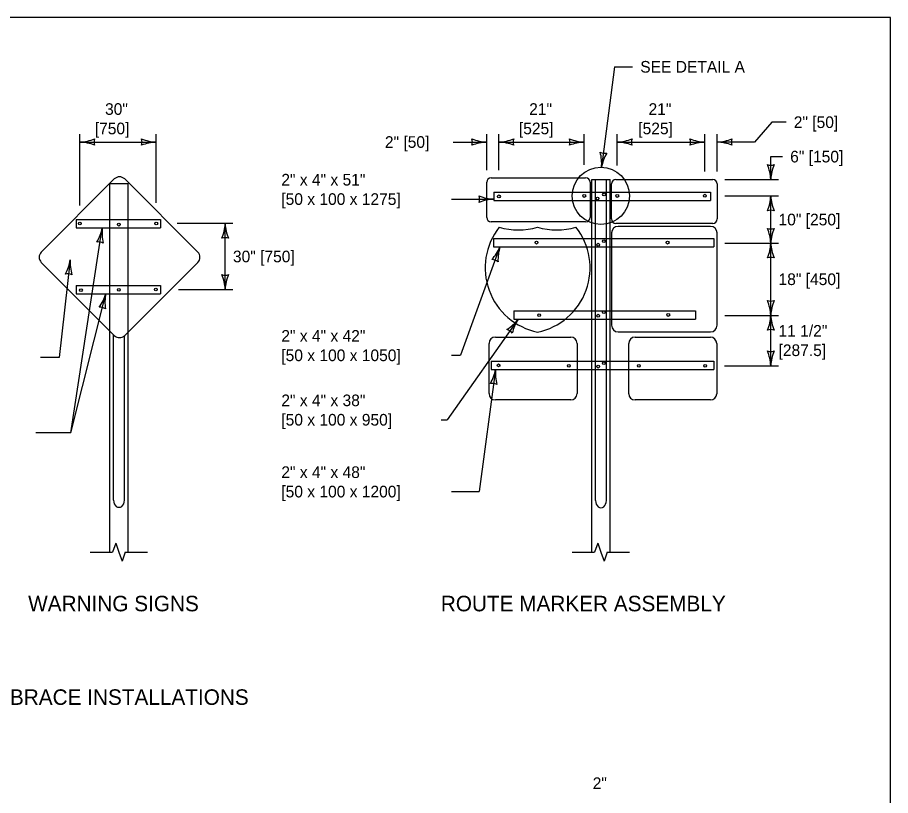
# Model space of a CAD drawing. Extents: x 49991.4 to 50021, y 49987.6 to 50011.4.
# Drawn here: x 50004.115 to 50008.615, y 50007.252 to 50011.263 of the extents above; entities that cross this region are included whole.
import ezdxf

# ---------------------------------------------------------------- set-up
doc = ezdxf.new("R2010")
doc.units = 0
for name, color, linetype in [('Level 1', 7, 'Continuous'), ('Level 2', 7, 'Continuous'), ('Level 3', 7, 'Continuous'), ('Level 4', 7, 'Continuous'), ('Level 6', 7, 'Continuous')]:
    doc.layers.add(name, color=color, linetype=linetype)

msp = doc.modelspace()

# ---------------------------------------------------------------- linework, layer by layer
at = {"layer": 'Level 1'}
for p, q in [((50006.5559, 50010.4356), (50007.0433, 50010.4356)), ((50004.6142, 50010.4302), (50004.2379, 50010.0538)), ((50005.0444, 50010.0538), (50004.668, 50010.4302)), ((50006.5332, 50010.2317), (50006.5332, 50010.413)), ((50007.0659, 50010.413), (50007.0659, 50010.2317)), ((50007.0744, 50008.5067), (50007.0744, 50010.4281)), ((50007.0744, 50010.4281), (50007.1696, 50010.4281)), ((50007.0942, 50008.7725), (50007.0942, 50010.4281)), ((50007.1502, 50008.7725), (50007.1502, 50010.4281)), ((50007.1696, 50008.5067), (50007.1696, 50010.4281)), ((50007.176, 50010.2241), (50007.176, 50010.4054)), ((50007.1988, 50010.4281), (50007.6985, 50010.4281)), ((50007.7212, 50010.4054), (50007.7212, 50010.2241)), ((50007.0433, 50010.209), (50006.5559, 50010.209)), ((50007.6985, 50010.2014), (50007.1988, 50010.2014)), ((50007.6868, 50010.1861), (50007.2108, 50010.1861)), ((50007.1768, 50010.1521), (50007.1768, 50009.6761)), ((50007.7208, 50009.6761), (50007.7208, 50010.1521)), ((50004.2379, 50010.0001), (50004.6142, 50009.6237)), ((50004.9757, 50009.9314), (50005.0444, 50010.0001)), ((50004.668, 50009.6237), (50004.9757, 50009.9315)), ((50004.5905, 50008.5067), (50004.5905, 50009.6474)), ((50004.6103, 50008.7748), (50004.6103, 50009.6276)), ((50004.6857, 50008.5067), (50004.6857, 50009.6414)), ((50007.2108, 50009.6421), (50007.6868, 50009.6421)), ((50004.6663, 50008.7748), (50004.6663, 50009.6221)), ((50006.5456, 50009.324), (50006.5456, 50009.583)), ((50006.578, 50009.6154), (50006.9665, 50009.6154)), ((50006.9989, 50009.583), (50006.9989, 50009.324)), ((50007.2656, 50009.3235), (50007.2656, 50009.5825)), ((50007.298, 50009.6148), (50007.6866, 50009.6148)), ((50007.719, 50009.5825), (50007.719, 50009.3235)), ((50006.9665, 50009.2916), (50006.578, 50009.2916)), ((50007.6866, 50009.2911), (50007.298, 50009.2911))]:
    msp.add_line(p, q, dxfattribs=at)
msp.add_lwpolyline([(50008.6146, 50011.2628), (50000.3356, 50011.2628), (50000.3356, 50000.0624), (50008.6146, 50000.0624)], close=True, dxfattribs=at)
for centre in [(50006.5965, 50010.3405), (50007.0364, 50010.3427), (50007.1382, 50010.3505), (50007.2064, 50010.3427), (50007.6571, 50010.3441), (50007.1046, 50010.3297), (50004.4369, 50010.2005), (50004.6373, 50010.1951), (50004.8305, 50010.2005), (50006.7905, 50010.1022), (50007.1083, 50010.0914), (50007.1372, 50010.1094), (50007.4657, 50010.1022), (50004.4423, 50009.8575), (50004.6373, 50009.8593), (50004.8287, 50009.8611), (50006.8038, 50009.7288), (50007.1083, 50009.7255), (50007.1372, 50009.7435), (50007.4693, 50009.7294), (50006.5948, 50009.4698), (50006.9567, 50009.467), (50007.1083, 50009.4631), (50007.1372, 50009.4811), (50007.3173, 50009.467), (50007.6593, 50009.467)]:
    msp.add_circle(centre, 0.0072, dxfattribs=at)
for centre, radius, start, end in [((50004.6411, 50010.4033), 0.038, 45.0001, 134.9999), ((50006.5559, 50010.413), 0.0227, 90, 180), ((50007.0433, 50010.413), 0.0227, 0, 90), ((50007.1987, 50010.4054), 0.0227, 90, 180), ((50007.6985, 50010.4054), 0.0227, 0, 90), ((50006.5559, 50010.2316), 0.0227, 180, 270), ((50007.0433, 50010.2316), 0.0227, 270, 0), ((50007.1987, 50010.2241), 0.0227, 180, 270), ((50007.6985, 50010.2241), 0.0227, 270, 0), ((50006.8633, 50009.9724), 0.338, 141.669, 258.4631), ((50006.6969, 50010.5053), 0.338, 253.0091, 286.9909), ((50006.7281, 50009.9724), 0.338, 281.5369, 38.331), ((50006.8945, 50010.5053), 0.338, 253.0091, 286.9909), ((50007.2108, 50010.1521), 0.034, 90, 180), ((50007.6868, 50010.1521), 0.034, 0, 90), ((50004.2648, 50010.027), 0.038, 134.9999, 225.0001), ((50005.0175, 50010.027), 0.038, 314.9999, 45.0001), ((50007.2108, 50009.6761), 0.034, 180, 270), ((50007.6868, 50009.6761), 0.034, 270, 0), ((50004.6411, 50009.6506), 0.038, 225.0001, 314.9999), ((50006.578, 50009.583), 0.0324, 90, 180), ((50006.9665, 50009.583), 0.0324, 0, 90), ((50007.298, 50009.5825), 0.0324, 90, 180), ((50007.6866, 50009.5825), 0.0324, 0, 90), ((50006.578, 50009.324), 0.0324, 180, 270), ((50006.9665, 50009.324), 0.0324, 270, 0), ((50007.298, 50009.3235), 0.0324, 180, 270), ((50007.6866, 50009.3235), 0.0324, 270, 0)]:
    msp.add_arc(centre, radius, start, end, dxfattribs=at)
for centre in [(50004.6383, 50008.7748), (50007.1222, 50008.7725)]:
    msp.add_ellipse(centre, major_axis=(0, -0.0368), ratio=0.761048, start_param=4.712389, end_param=7.853982, dxfattribs=at)
at = {"layer": 'Level 3'}
for p, q in [((50007.1928, 50011.0085), (50007.1253, 50010.4907)), ((50007.1928, 50011.0085), (50007.2847, 50011.0085)), ((50008.0036, 50010.723), (50007.9131, 50010.6207)), ((50008.0759, 50010.723), (50008.0036, 50010.723)), ((50004.4369, 50010.2929), (50004.4369, 50010.6607)), ((50004.8305, 50010.3076), (50004.8305, 50010.6607)), ((50006.5332, 50010.4756), (50006.5332, 50010.6607)), ((50006.5965, 50010.4756), (50006.5965, 50010.6607)), ((50007.0364, 50010.5033), (50007.0364, 50010.6607)), ((50007.2064, 50010.4995), (50007.2064, 50010.6607)), ((50007.6571, 50010.4681), (50007.6571, 50010.6607)), ((50007.7212, 50010.4681), (50007.7212, 50010.6607)), ((50004.4369, 50010.6207), (50004.8305, 50010.6207)), ((50006.3598, 50010.6207), (50006.5332, 50010.6207)), ((50006.5965, 50010.6207), (50007.0364, 50010.6207)), ((50007.0164, 50010.6207), (50007.0164, 50010.6207)), ((50007.2064, 50010.6207), (50007.6571, 50010.6207)), ((50007.9131, 50010.6207), (50007.7212, 50010.6207)), ((50007.9974, 50010.4281), (50007.9974, 50010.5456)), ((50007.9974, 50010.5456), (50008.0574, 50010.5456)), ((50007.7612, 50010.4281), (50008.0374, 50010.4281)), ((50006.3522, 50010.3266), (50006.5702, 50010.3266)), ((50007.7612, 50010.3427), (50008.0374, 50010.3427)), ((50007.9974, 50010.0997), (50007.9974, 50010.3427)), ((50004.3904, 50009.1222), (50004.5521, 50010.1779)), ((50005.2256, 50010.2005), (50004.9377, 50010.2005)), ((50005.1856, 50009.8611), (50005.1856, 50010.2005)), ((50006.6019, 50010.0806), (50006.3983, 50009.5215)), ((50007.7608, 50010.0997), (50008.0374, 50010.0997)), ((50007.9974, 50009.7273), (50007.9974, 50010.0997)), ((50004.3874, 50010.014), (50004.3307, 50009.5098)), ((50004.9452, 50009.8611), (50005.2256, 50009.8611)), ((50004.3904, 50009.1222), (50004.5706, 50009.8385)), ((50007.7608, 50009.7273), (50008.0374, 50009.7273)), ((50007.9974, 50009.4677), (50007.9974, 50009.7273)), ((50006.6954, 50009.7071), (50006.3302, 50009.1892)), ((50004.3307, 50009.5098), (50004.2343, 50009.5098)), ((50006.3522, 50009.5215), (50006.3983, 50009.5215)), ((50006.579, 50009.4487), (50006.4947, 50008.819)), ((50007.759, 50009.4677), (50008.0374, 50009.4677)), ((50006.2983, 50009.1892), (50006.3302, 50009.1892)), ((50004.3904, 50009.1222), (50004.2096, 50009.1222)), ((50006.3522, 50008.819), (50006.4947, 50008.819))]:
    msp.add_line(p, q, dxfattribs=at)
msp.add_circle((50007.122, 50010.343), 0.1476, dxfattribs=at)
for centre, radius, start, end in [((50004.4254, 50010.8534), 0.233, 272.8273, 292.0772), ((50004.4277, 50010.3986), 0.2223, 67.456, 87.6395), ((50004.5651, 50010.6207), 0.0548, 162.1388, 197.8612), ((50004.8397, 50010.8428), 0.2223, 247.456, 267.6395), ((50004.7023, 50010.6207), 0.0548, 342.1388, 17.8612), ((50004.842, 50010.388), 0.233, 92.8273, 112.0772), ((50006.5424, 50010.8428), 0.2223, 247.456, 267.6395), ((50006.405, 50010.6207), 0.0548, 342.1388, 17.8612), ((50006.5447, 50010.388), 0.233, 92.8273, 112.0772), ((50006.585, 50010.8534), 0.233, 272.8273, 292.0772), ((50006.5873, 50010.3986), 0.2223, 67.456, 87.6395), ((50006.7247, 50010.6207), 0.0548, 162.1388, 197.8612), ((50007.0456, 50010.8428), 0.2223, 247.456, 267.6395), ((50006.9082, 50010.6207), 0.0548, 342.1388, 17.8612), ((50007.0479, 50010.388), 0.233, 92.8273, 112.0772), ((50007.1949, 50010.8534), 0.233, 272.8273, 292.0772), ((50007.1972, 50010.3986), 0.2223, 67.456, 87.6395), ((50007.3346, 50010.6207), 0.0548, 162.1388, 197.8612), ((50007.6663, 50010.8428), 0.2223, 247.456, 267.6395), ((50007.5289, 50010.6207), 0.0548, 342.1388, 17.8612), ((50007.6686, 50010.388), 0.233, 92.8273, 112.0772), ((50007.7097, 50010.8534), 0.233, 272.8273, 292.0772), ((50007.712, 50010.3986), 0.2223, 67.456, 87.6395), ((50007.8494, 50010.6207), 0.0548, 162.1388, 197.8612), ((50007.1419, 50010.6177), 0.0548, 244.7118, 280.4341), ((50006.893, 50010.5093), 0.233, 355.4003, 14.6501), ((50007.3444, 50010.4528), 0.2223, 150.029, 170.2125), ((50007.9974, 50010.5563), 0.0548, 252.1388, 287.8612), ((50007.7647, 50010.4166), 0.233, 2.8273, 22.0772), ((50008.2195, 50010.4189), 0.2223, 157.456, 177.6395), ((50006.5794, 50010.5487), 0.2223, 247.456, 267.6395), ((50006.442, 50010.3266), 0.0548, 342.1388, 17.8612), ((50006.5817, 50010.0939), 0.233, 92.8273, 112.0772), ((50007.7753, 50010.3519), 0.2223, 337.456, 357.6395), ((50008.2301, 50010.3542), 0.233, 182.8273, 202.0772), ((50007.9974, 50010.2145), 0.0548, 72.1388, 107.8612), ((50004.3339, 50010.2206), 0.2223, 328.7459, 348.9294), ((50004.7839, 50010.154), 0.233, 174.1172, 193.3671), ((50004.9635, 50010.2097), 0.2223, 337.456, 357.6395), ((50005.4183, 50010.212), 0.2329, 182.8273, 202.0772), ((50007.9974, 50010.2279), 0.0548, 252.1388, 287.8612), ((50007.7647, 50010.0882), 0.233, 2.8273, 22.0772), ((50008.2195, 50010.0905), 0.2223, 157.456, 177.6395), ((50005.1856, 50010.0723), 0.0548, 72.1388, 107.8612), ((50004.5327, 50010.0512), 0.0548, 63.4287, 99.1511), ((50006.3963, 50010.1652), 0.2223, 317.4461, 337.6296), ((50006.8245, 50010.0118), 0.233, 162.8174, 182.0672), ((50007.7753, 50010.1089), 0.2223, 337.456, 357.6395), ((50008.2301, 50010.1112), 0.233, 182.8273, 202.0772), ((50004.1677, 50010.0479), 0.2223, 331.0398, 351.2233), ((50004.6199, 50009.9994), 0.233, 176.4111, 195.6609), ((50006.558, 50009.9601), 0.0548, 52.1289, 87.8513), ((50007.9974, 50009.9715), 0.0548, 72.1388, 107.8612), ((50004.3731, 50009.8866), 0.0548, 65.7226, 101.4449), ((50005.1856, 50009.9893), 0.0548, 252.1388, 287.8612), ((50004.9529, 50009.8496), 0.2329, 2.8273, 22.0772), ((50005.4077, 50009.8519), 0.2223, 157.456, 177.6395), ((50004.3574, 50009.9016), 0.2223, 323.3325, 343.516), ((50004.7991, 50009.7929), 0.233, 168.7038, 187.9536), ((50004.5393, 50009.7142), 0.0548, 58.0153, 93.7376), ((50007.9974, 50009.8555), 0.0548, 252.1388, 287.8612), ((50007.7647, 50009.7158), 0.233, 2.8273, 22.0772), ((50008.2195, 50009.7181), 0.2223, 157.456, 177.6395), ((50007.7753, 50009.7365), 0.2223, 337.456, 357.6395), ((50008.2301, 50009.7388), 0.233, 182.8273, 202.0772), ((50006.5191, 50009.8426), 0.2223, 302.2671, 322.4506), ((50006.8922, 50009.5824), 0.233, 147.6384, 166.8882), ((50006.6215, 50009.6023), 0.0548, 36.9499, 72.6722), ((50007.9974, 50009.5991), 0.0548, 72.1388, 107.8612), ((50007.9974, 50009.5959), 0.0548, 252.1388, 287.8612), ((50007.7647, 50009.4562), 0.233, 2.8273, 22.0772), ((50008.2195, 50009.4585), 0.2223, 157.456, 177.6395), ((50006.36, 50009.4872), 0.2223, 329.8322, 350.0157), ((50006.8112, 50009.4292), 0.233, 175.2035, 194.4533), ((50006.562, 50009.3216), 0.0548, 64.515, 100.2373)]:
    msp.add_arc(centre, radius, start, end, dxfattribs=at)
at = {"layer": 'Level 4'}
for p, q in [((50004.5905, 50009.6474), (50004.5905, 50010.4065)), ((50004.5905, 50010.4065), (50004.6857, 50010.4065)), ((50004.6857, 50009.6414), (50004.6857, 50010.4065)), ((50006.5702, 50010.3622), (50007.686, 50010.3622)), ((50006.5702, 50010.3622), (50006.5702, 50010.3189)), ((50007.686, 50010.3622), (50007.686, 50010.3189)), ((50006.5702, 50010.3189), (50007.686, 50010.3189)), ((50004.417, 50010.2212), (50004.417, 50010.1779)), ((50004.417, 50010.2212), (50004.8521, 50010.2212)), ((50004.8521, 50010.2212), (50004.8521, 50010.1779)), ((50004.417, 50010.1779), (50004.8521, 50010.1779)), ((50006.5677, 50010.1239), (50007.7035, 50010.1239)), ((50006.5677, 50010.1239), (50006.5677, 50010.0806)), ((50007.7035, 50010.1239), (50007.7035, 50010.0806)), ((50006.5677, 50010.0806), (50007.7035, 50010.0806)), ((50004.417, 50009.8818), (50004.417, 50009.8385)), ((50004.417, 50009.8818), (50004.8521, 50009.8818)), ((50004.8521, 50009.8818), (50004.8521, 50009.8385)), ((50004.417, 50009.8385), (50004.8521, 50009.8385)), ((50006.6738, 50009.7504), (50007.609, 50009.7504)), ((50006.6738, 50009.7504), (50006.6738, 50009.7071)), ((50007.609, 50009.7504), (50007.609, 50009.7071)), ((50006.6738, 50009.7071), (50007.609, 50009.7071)), ((50006.5566, 50009.492), (50007.7035, 50009.492)), ((50006.5566, 50009.492), (50006.5566, 50009.4487)), ((50007.7035, 50009.492), (50007.7035, 50009.4487)), ((50006.5566, 50009.4487), (50007.7035, 50009.4487))]:
    msp.add_line(p, q, dxfattribs=at)
at = {"layer": 'Level 6'}
for p, q in [((50004.6219, 50008.5524), (50004.6057, 50008.5067)), ((50004.6219, 50008.5524), (50004.6381, 50008.5067)), ((50007.1058, 50008.5524), (50007.0896, 50008.5067)), ((50007.1058, 50008.5524), (50007.122, 50008.5067)), ((50004.4905, 50008.5067), (50004.6057, 50008.5067)), ((50004.6381, 50008.5067), (50004.6543, 50008.461)), ((50004.6705, 50008.5067), (50004.6543, 50008.461)), ((50004.6705, 50008.5067), (50004.7857, 50008.5067)), ((50006.9744, 50008.5067), (50007.0896, 50008.5067)), ((50007.122, 50008.5067), (50007.1382, 50008.461)), ((50007.1544, 50008.5067), (50007.1382, 50008.461)), ((50007.1544, 50008.5067), (50007.2696, 50008.5067))]:
    msp.add_line(p, q, dxfattribs=at)

# ---------------------------------------------------------------- texts
at = {"layer": 'Level 2'}
for s, height, p in [('SEE DETAIL A', 0.06, (50007.3247, 50010.9785)), ('30"', 0.06, (50004.5665, 50010.7607)), ('21"', 0.06, (50006.7522, 50010.7607)), ('21"', 0.06, (50007.3675, 50010.7607)), ('2" [50]', 0.06, (50008.1159, 50010.693)), ('[750]', 0.06, (50004.5136, 50010.6607)), ('[525]', 0.06, (50006.6993, 50010.6607)), ('[525]', 0.06, (50007.3146, 50010.6607)), ('2" [50]', 0.06, (50006.0087, 50010.5907)), ('6" [150]', 0.06, (50008.0974, 50010.5156)), ('2" x 4" x 51"', 0.06, (50005.4749, 50010.3966)), ('[50 x 100 x 1275]', 0.06, (50005.4749, 50010.2966)), ('10" [250]', 0.06, (50008.0374, 50010.1912)), ('30" [750]', 0.06, (50005.2256, 50010.0008)), ('18" [450]', 0.06, (50008.0374, 50009.8835)), ('11 1/2"', 0.06, (50008.0374, 50009.6175)), ('2" x 4" x 42"', 0.06, (50005.4749, 50009.5915)), ('[287.5]', 0.06, (50008.0374, 50009.5175)), ('[50 x 100 x 1050]', 0.06, (50005.4749, 50009.4915)), ('2" x 4" x 38"', 0.06, (50005.4749, 50009.2592)), ('[50 x 100 x 950]', 0.06, (50005.4749, 50009.1592)), ('2" x 4" x 48"', 0.06, (50005.4749, 50008.889)), ('[50 x 100 x 1200]', 0.06, (50005.4749, 50008.789)), ('WARNING SIGNS', 0.08, (50004.1701, 50008.2019)), ('ROUTE MARKER ASSEMBLY', 0.08, (50006.2969, 50008.2019)), ('WOOD BACKBRACE INSTALLATIONS', 0.08, (50003.4106, 50007.7197)), ('2"', 0.06, (50007.0796, 50007.2858))]:
    msp.add_text(s, height=height, dxfattribs=at).set_placement(p)

doc.saveas('drawing.dxf')
